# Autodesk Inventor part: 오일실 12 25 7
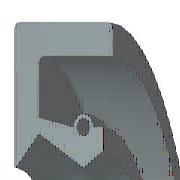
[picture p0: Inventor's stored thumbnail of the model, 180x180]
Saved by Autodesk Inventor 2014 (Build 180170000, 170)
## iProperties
IsCustomPart: 1
Created: 2012-02
Part Number: 오일실 12 25 7
Material: 고무
Description: 오일-실
Document SubType Name: Modeling
Standard: KS B 2804
Designer: test
Standards Organization: KS
Language: ko-KR
Size Designation: D - 12 25 7
Categories: <MemberInstance><Categories><Category DisplayName="샤프트 부품" InternalName="7f7aeb1f-a693-4053-b835-cee3144e0d98" Mnemonic="SHFT"><Category DisplayName="실링" Intern
Density: 0.93 g/cm^3
Appearance: 고무 - 검은색 - 버전 1.1
Author: test
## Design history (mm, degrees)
revolve "본체" stored, may be unused: angle "d17" = 90 deg
revolve "스프링1" stored, may be unused: angle "d18" = 90 deg
body "Solid1"
sketch "스케치1"
  geometry: L1 (0, 12.5)-(7, 12.5); L2 (7, 10.75)-(1.75, 10.75); L3 (1.75, 7.75)-(4.9, 6); L4 (4.9, 6)-(0, 6); L5 (0, 0)-(9.586, 0) reference; L6 (4.9, 6)-(6.3, 6.875); L7 (0, 18)-(0, -3) reference; L8 (-1.941, 0)-(11.507, 0) reference; L9 (4.2, 8.1)-(1.75, 8.59); L10 (1.75, 8.59)-(1.75, 10.75); L11 (0, 12.5)-(0, 6.088); L12 (4.9, 6)-(0, 6); L13 (1.75, 7.75)-(0.152, 6.028); L14 (7, 12.5)-(7, 10.75); L15 (5.6, 8.1)-(6.3, 8.1); L16 (6.3, 8.1)-(6.3, 6.875); C1 r 0.455 at (4.9, 8.1); A1 r 0.7 centre (4.9, 8.1) between (5.6, 8.1) and (4.2, 8.1); A2 r 0.088 centre (0.088, 6.088) between (0, 6.088) and (0.152, 6.028); 1 further point
  constraints: 28 end point, 5 horizontal alignment, 5 point on line, 4 point on circle, 4 vertical alignment, 3 centre point, 3 tangent, 2 collinear, 2 horizontal, 2 perpendicular, 1 coincident, 1 parallel
  dimensions: "d0" = 25 diameter of L1 L5 (= SD2); "d1" = 1.75 distance of L1.end L2.start (= SD); "d2" = 0.91 diameter of C1 (= SPDI); "d3" = 1.4 diameter of A1 (= SPDA); "d4" = 12 diameter of L3.end L5 (= NND); "d5" = 15.5 diameter of L3.start L5 (= TKDM); "d7" = 17.18 diameter of L9.end L5 (= TKDM + 0.24 x SWDT); "d8" = 1.75 distance between parallel lines of L11 L10 (= SD); "d9" = 4.9 distance from line of L11 C1.centre (= SPDST); "d10" = 16.2 diameter of C1.centre L5 (= HLDM); "d11" = 0.0875 radius of A2 (= 0.25 x LAB); "d12" = 6.3 distance between parallel lines of L11 L16 (= SDI); "d13" = 13.75 diameter of L6.end L5 (= ABDM); "d14" = 7 distance from line of L11 L1.end (= SWDT)
fillet "모깎기1" dims "d6" = 0.3 (= RR)
other parameters: "SD2" = 25 [user parameter; used in 1 equation term], "SWDT" = 7 [user parameter; used in 2 equation terms], "RR" = 0.3 [user parameter; used in 1 equation term], "SD" = 1.75 [user parameter; used in 2 equation terms], "NND" = 12 [user parameter; used in 1 equation term], "SPDA" = 1.4 [user parameter; used in 1 equation term], "SPDI" = 0.91 [user parameter; used in 1 equation term], "TKDM" = 15.5 [user parameter; used in 2 equation terms], "HLDM" = 16.2 [user parameter; used in 1 equation term], "ABDM" = 13.75 [user parameter; used in 1 equation term], "SDI" = 6.3 [user parameter; used in 1 equation term], "SPDST" = 4.9 [user parameter; used in 1 equation term], "LAB" = 0.35 [user parameter; used in 1 equation term], "d15" = 0, "d16" = 0, "d19" = 0
